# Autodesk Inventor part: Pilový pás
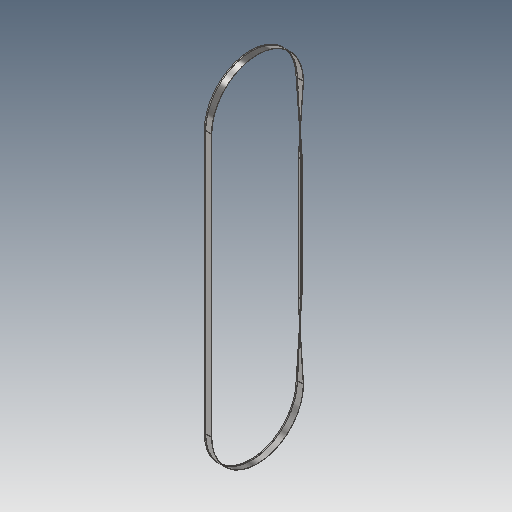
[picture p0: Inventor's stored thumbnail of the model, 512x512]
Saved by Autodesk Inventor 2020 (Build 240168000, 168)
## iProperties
Created: 2025-03
Part Number: Pilový pás
Material: Ocel
Document SubType Name: Modeling
Designer: doma
Density: 7.85 g/cm^3
Appearance: Ocel – leštěná
Mass: 332.397 g
Surface Area: 963.879 cm^2
Volume: 42.3435 cm^3
Author: doma
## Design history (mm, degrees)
node "Pracovní rovina1"
sketch "Náčrt1"
  geometry: L1 (19, 130)-(2, 130); L2 (19, 130)-(19, 130.9); L3 (19, 130.9)-(2, 130.9); L4 (-1, 131.2)-(2, 130.9); L5 (-1, 129.7)-(2, 130); L6 (2, 130.9)-(2, 130); L7 (-1, 131.2)-(-1, 129.7); L8 (2, 130.45)-(0.439, 130.45); L9 (19, 132.5)-(19, -132.5) reference; L10 (22, 132.5)-(22, -132.5) reference; L11 (2, 130)-(2, -130) reference; L12 (19, 130)-(19, -130) reference; 1 further point
  constraints: 16 end point, 2 perpendicular, 2 vertical, 1 horizontal, 1 midpoint, 1 point on line, 1 other
  dimensions: "d0" = 0.9 distance of L1.start L2.end; "d4" = 1.5 distance of L5.start L4.start; "d5" = 3 distance from line of L3.end L7
  node "Referenční1"
  node "Referenční2"
  node "Referenční3"
  node "Referenční4"
node "Pracovní rovina2"
  node "Pracovní osa1"
sketch "Náčrt2"
  geometry: L1 (25, 130)-(8, 130); L2 (8, 130)-(8, 130.9); L3 (8, 130.9)-(25, 130.9); L4 (25, 130.9)-(25, 130); L5 (25, 130.45)-(27, 130.45); L6 (25, 130.9)-(28, 131.2); L7 (28, 131.2)-(28, 129.7); L8 (28, 129.7)-(25, 130); C1 r 0 at (25, 0) reference; C2 r 0 at (8, 0) reference; C3 r 0 at (8, 0) reference; 1 further point
  constraints: 16 end point, 1 horizontal, 1 midpoint, 1 parallel, 1 tangent, 1 vertical, 3 other
  dimensions: "d7" = 0.9 distance of L1.end L2.end; "d8" = 1.5 distance of L6.end L7.end (= d4); "d9" = 3 distance from line of L7 L1.start (= d5)
  node "Referenční5"
  node "Referenční6"
  node "Referenční7"
sketch "Náčrt3"
  geometry: L1 (25, -130)-(8, -130); L2 (8, -130)-(8, -130.9); L3 (8, -130.9)-(25, -130.9); L4 (25, -130.9)-(28, -131.2); L5 (28, -131.2)-(28, -129.7); L6 (28, -129.7)-(25, -130); L7 (25, -130)-(25, -130.9); L8 (25, -130.45)-(26.612, -130.45); C1 r 0 at (25, 0) reference; C2 r 0 at (8, 0) reference; 1 further point
  constraints: 16 end point, 1 horizontal, 1 midpoint, 1 parallel, 1 perpendicular, 1 vertical, 4 other
  dimensions: "d10" = 0.9 distance of L1.end L2.end; "d11" = 3 distance from line of L3.end L5 (= d5); "d12" = 1.5 distance of L4.end L5.end (= d4)
  node "Referenční8"
  node "Referenční9"
node "Pracovní rovina3"
  node "Pracovní osa2"
sketch "Náčrt5"
  geometry: L1 (25, 130)-(8, 130); L2 (8, 130)-(8, 130.9); L3 (8, 130.9)-(25, 130.9); L4 (25, 130.9)-(28, 131.2); L5 (28, 131.2)-(28, 129.7); L6 (28, 129.7)-(25, 130); L7 (25, 130.9)-(25, 130); L8 (25, 130.45)-(25.946, 130.45); 3 further points; 2 other entities
  constraints: 16 end point, 2 horizontal, 1 midpoint, 1 parallel, 1 perpendicular, 1 vertical, 5 other
  dimensions: "d17" = 0.9 distance of L1.end L2.end; "d18" = 1.5 distance of L4.end L5.end (= d4); "d19" = 3 distance from line of L5 L1.start (= d5)
  node "Referenční12"
  node "Referenční13"
node "Pracovní rovina4"
sketch "Náčrt11"
  geometry: L1 (2, -876)-(19, -876); L2 (19, -876)-(19, -876.9); L3 (19, -876.9)-(2, -876.9); L4 (2, -876)-(-1, -875.7); L5 (-1, -875.7)-(-1, -877.2); L6 (-1, -877.2)-(2, -876.9); L7 (2, -876)-(2, -876.9); L8 (2, -876.45)-(-0.24, -876.45); C1 r 0 at (19, -746) reference; 3 further points; 2 other entities
  constraints: 16 end point, 3 horizontal, 2 vertical, 2 vertical alignment, 1 midpoint, 1 perpendicular, 3 other
  dimensions: "d36" = 0.9 distance of L1.end L2.end; "d39" = 3 distance from line of L5 L3.end (= d5); "d40" = 1.5 distance of L4.end L5.end (= d4); "d41" = 130 distance from line of point (2, -746) L1
  node "Referenční24"
  node "Referenční25"
  node "Referenční26"
node "Pracovní rovina5"
sketch "Náčrt12"
  geometry: L1 (6.5, 60)-(18.5, 60) reference; L2 (11.25, 79)-(11.25, 79) reference; L3 (11.75, 79)-(11.75, 64) reference; L4 (13.25, 64)-(13.25, 79) reference; L5 (11.25, 79)-(9.25, 79) reference; L6 (13.75, 79)-(15.75, 79) reference; L7 (18.5, 60)-(6.5, 60) reference; L8 (7.5, 64)-(17.5, 64) reference; L9 (12.5, 64)-(12.5, 81.43); L10 (12.95, 64)-(12.05, 64); L11 (12.05, 64)-(12.05, 81); L12 (12.95, 64)-(12.95, 81); L13 (12.05, 81)-(11.75, 84); L14 (11.75, 84)-(13.25, 84); L15 (13.25, 84)-(12.95, 81); 2 further points
  constraints: 14 end point, 3 point on line, 2 midpoint, 2 parallel, 1 horizontal, 1 vertical, 1 other
  dimensions: "d51" = 0.9 distance of L10.start L10.end; "d52" = 17 distance of L10.end L11.end; "d53" = 1.5 distance of L13.end L14.end (= d4); "d54" = 3 distance from line of L12.end L14 (= d5)
  node "Referenční27"
  node "Referenční28"
  node "Referenční29"
  node "Referenční30"
  node "Referenční31"
  node "Referenční32"
  node "Referenční33"
  node "Referenční34"
node "Pracovní rovina6" dims "d36" = 0.9, "d39" = 3 (= d5), "d40" = 1.5 (= d4), "d41" = 130
sketch "Náčrt13" dims "d36" = 0.9, "d39" = 3 (= d5), "d40" = 1.5 (= d4), "d41" = 130
  geometry: L1 (13.25, 79)-(13.25, 64) reference; L2 (11.75, 64)-(11.75, 79) reference; L3 (18.5, 63)-(6.5, 63) reference; L4 (7.6, 64)-(17.6, 64) reference; L5 (13.05, 64)-(13.05, 81) reference; L6 (12.15, 64)-(13.05, 64) reference; L7 (12.15, 64)-(12.15, 81) reference; L8 (13.35, 84)-(11.85, 84) reference; L9 (13.05, 81)-(13.35, 84) reference; L10 (11.85, 84)-(12.15, 81) reference
  node "Referenční35"
  node "Referenční36"
  node "Referenční37"
  node "Referenční38"
sketch "3D náčrt3" dims "d36" = 0.9, "d39" = 3 (= d5), "d40" = 1.5 (= d4), "d41" = 130
sketch "3D náčrt4" dims "d36" = 0.9, "d39" = 3 (= d5), "d40" = 1.5 (= d4), "d41" = 130
feature "Šablonování2" sketch "3D náčrt4" dims "d72" = 0, "d73" = 90 deg, "d74" = 0, "d75" = 90 deg, "d76" = 0, "d77" = 90 deg
feature "Šablonování3" dims "d78" = 0, "d79" = 90 deg, "d80" = 0, "d81" = 90 deg, "d82" = 0, "d83" = 90 deg
  node "Hrany1"
sketch "3D náčrt5"
sketch "3D náčrt6"
feature "Šablonování4" sketch "3D náčrt6" dims "d84" = 0, "d85" = 90 deg, "d86" = 0, "d87" = 90 deg, "d88" = 0, "d89" = 90 deg
  node "Hrany2"
feature "Šablonování5" dims "d90" = 0, "d91" = 90 deg, "d92" = 0, "d93" = 90 deg, "d94" = 0, "d95" = 90 deg, "d96" = 0, "d97" = 90 deg
feature "Šablonování6" dims "d98" = 0, "d99" = 90 deg, "d100" = 0, "d101" = 90 deg, "d102" = 0, "d103" = 90 deg, "d104" = 0, "d105" = 90 deg
  node "Hrany3"
feature "Šablonování7" dims "d106" = 0, "d107" = 90 deg, "d108" = 0, "d109" = 90 deg, "d110" = 0, "d111" = 90 deg
  node "Hrany4"
  node "Hrany5"
node "Těleso3"
sketch "Náčrt6"
  geometry: L1 (25, -130)-(8, -130); L2 (8, -130)-(8, -130.9); L3 (8, -130.9)-(25, -130.9); L4 (25, -130.9)-(28, -131.2); L5 (28, -131.2)-(28, -129.7); L6 (28, -129.7)-(25, -130); L7 (25, -130)-(25, -130.9); L8 (25, -130.45)-(27.626, -130.45); 3 further points; 2 other entities
  constraints: 16 end point, 2 horizontal, 2 parallel, 1 midpoint, 1 perpendicular, 5 other
  dimensions: "d33" = 0.9 distance of L1.end L2.end; "d34" = 1.5 distance of L4.end L5.end (= d4); "d35" = 3 distance from line of L3.end L5 (= d5)
node "Referenční21"
node "Referenční22"
other parameters: "d6" = 90 deg, "d16" = 90 deg
